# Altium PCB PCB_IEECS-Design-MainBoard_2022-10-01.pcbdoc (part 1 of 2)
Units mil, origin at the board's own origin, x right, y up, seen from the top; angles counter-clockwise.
Board outline 4144.93 x 4242 mil, 2 copper layers (Top Layer, Bottom Layer); 143 components, 136 nets, 539 pads, 189 vias.
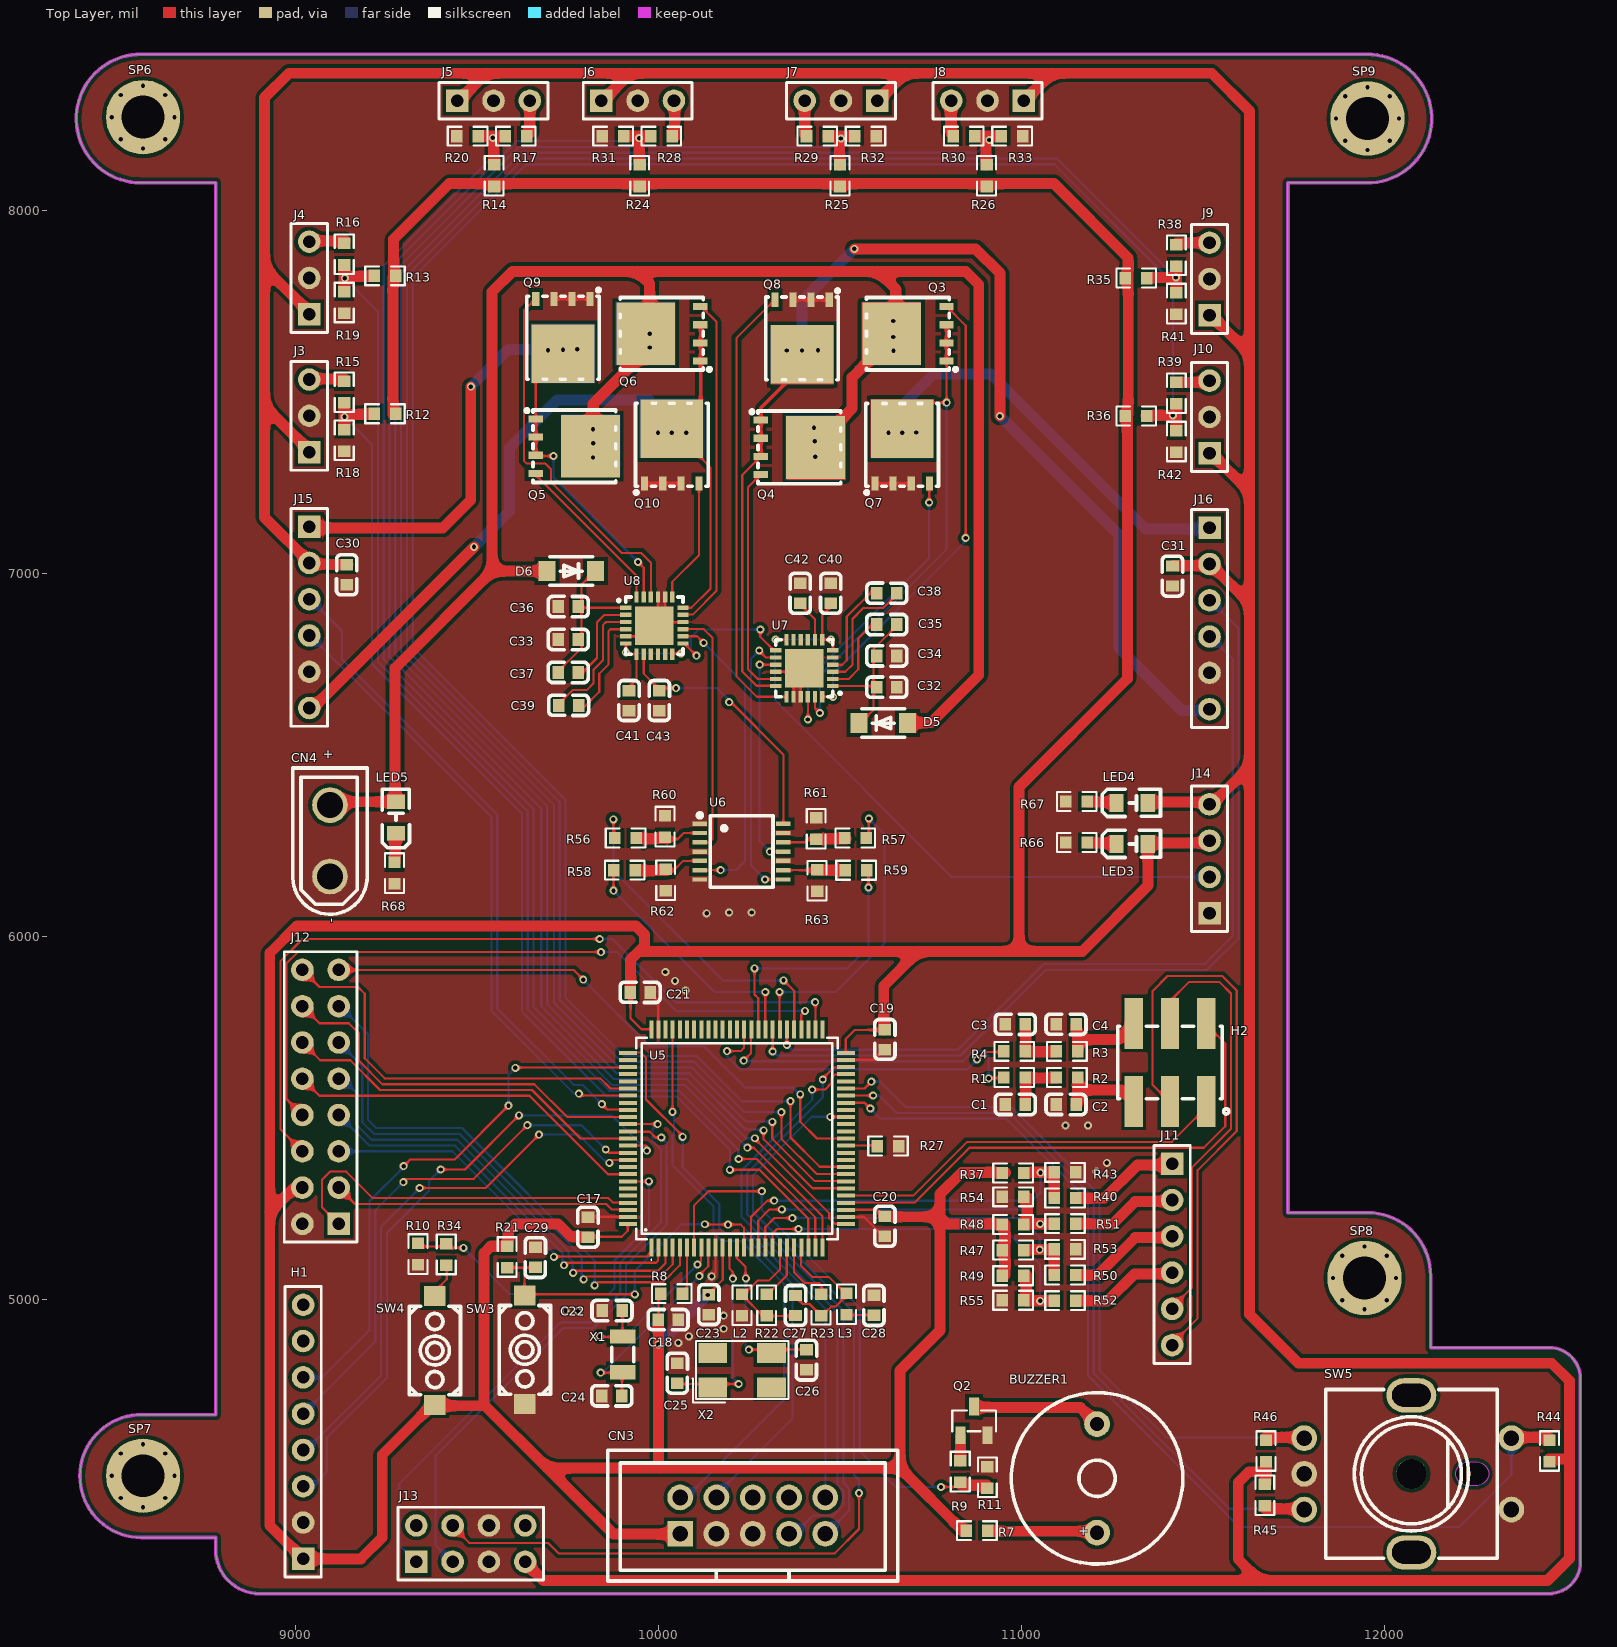
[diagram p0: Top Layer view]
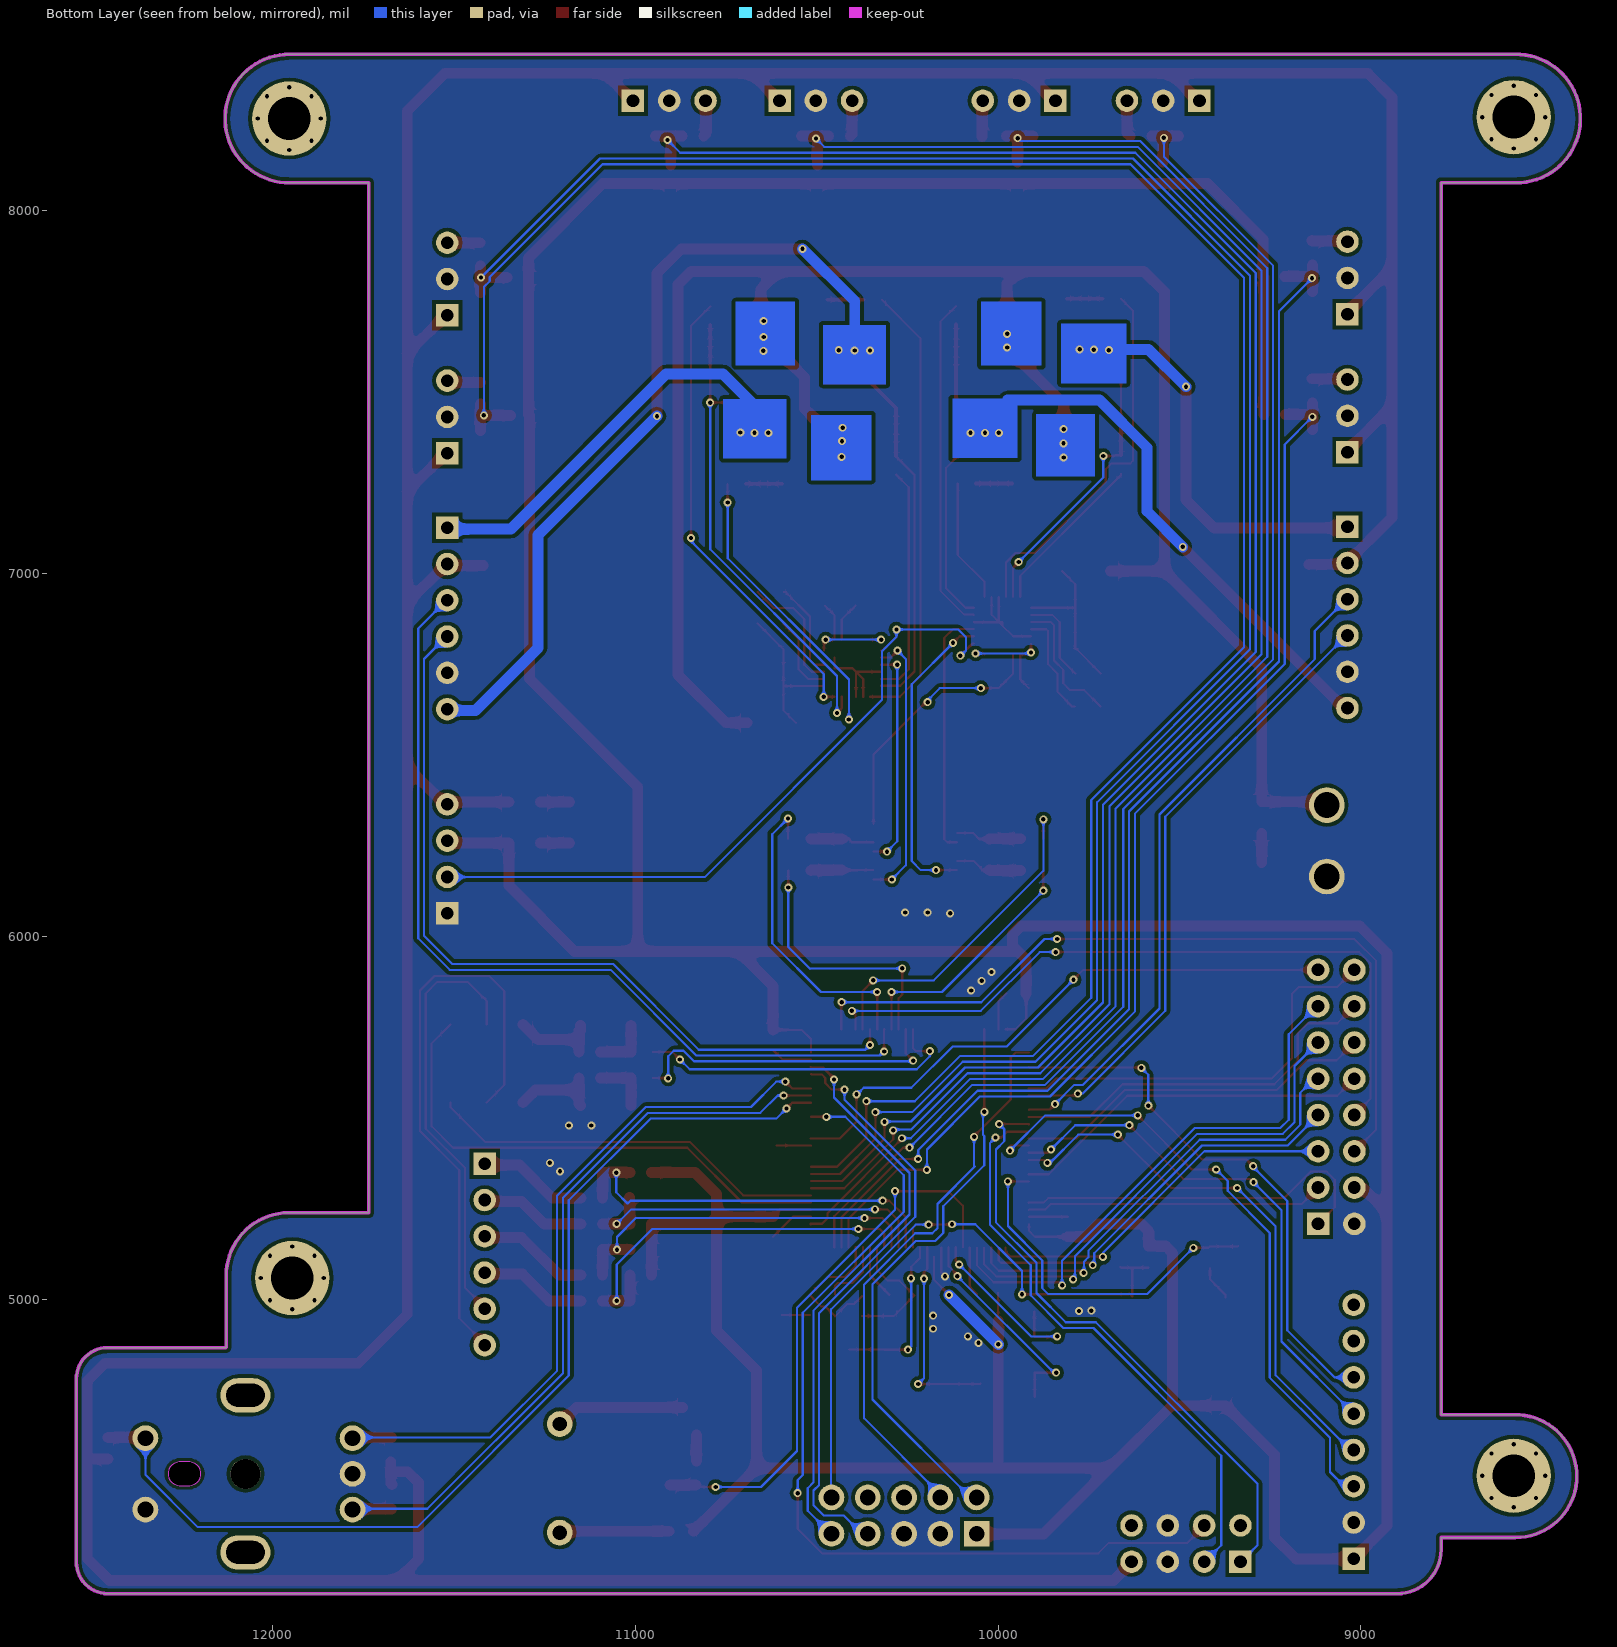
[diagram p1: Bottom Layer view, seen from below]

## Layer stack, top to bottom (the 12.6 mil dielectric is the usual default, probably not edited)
Top Solder: solder mask 0.4, Solder Resist, Dk 3.5
Top Layer: signal copper 1.4
Dielectric1: dielectric 12.6, FR-4, Dk 4.8
Bottom Layer: signal copper 1.4
Bottom Solder: solder mask 0.4, Solder Resist, Dk 3.5

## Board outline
8574.18,4343.58 8778.42,4343.58 8779,4343 8779,4310 ccw(c8900,4310) 8900,4189 12453,4189 ccw(c12453,4276) 12540,4276 12540,4781 ccw(c12454,4781) 12454,4867 12128.3,4867 12127.15,4868.15 12127.15,5065.04 ccw(c11953.18,5065.04) 11955,5239 11734,5239 11734,8077 11950.98,8077 ccw(c11953.18,8254) 11951,8431 8575,8431 ccw(c8572,8254) 8572,8076.97 8779,8076.97 8779,8038 8779,4682 8576,4682 ccw(c8574.18,4512.8)

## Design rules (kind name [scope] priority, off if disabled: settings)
Clearance [All] p1: gap=10 ignorepadtopadclearanceinfootprint=TRUE except(0: Arc-Hole Track-Hole SMDPad-Hole THPad-Hole Via-Hole Fill-Hole Poly-Hole Region-Hole Text-Hole)
Height [All] p1: minheight=0 maxheight=10000 prefheight=10000
PolygonConnect [All] p1: connectstyle=Direct reliefconductorwidth=10 reliefentries=4 polygonreliefangle="90 Angle" airgapwidth=10
RoutingVias [All] p1: holewidth=28 width=50 viastyle="Through Hole" minholewidth=28 minwidth=50 maxholewidth=28 maxwidth=50
SolderMaskExpansion [All] p1: expansion=4
Width [All] p1: maxlimit=30 minlimit=6 preferedwidth=10 minimp=50.000000 maximp=50.000000 favimp=50.000000
29 further rules are at their usual default settings.

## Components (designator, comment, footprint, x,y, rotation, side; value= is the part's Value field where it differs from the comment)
BUZZER1 "TMB12A03" Buzzer 11204,4510.61 r0 top
C1 "1nf" CAP0603 10983.66,5534 r0 top
C2 "100pf" CAP0603 11123.66,5534 r0 top
C3 "1nf" CAP0603 10983.66,5755 r0 top
C4 "100pf" CAP0603 11123.66,5755 r0 top
C17 "50V 100nF" CAP0603 9808,5200 r90 top
C18 "50V 100nF" CAP0603 10027,4941 r0 top
C19 "50V 100nF" CAP0603 10620,5715 r270 top
C20 "50V 100nF" CAP0603 10620,5200 r270 top
C21 "50V 100nF" CAP0603 9950,5843 r0 top
C22 "50V 12pF" CAP0603 9872.44,4966 r0 top
C23 "50V 100nF" CAP0603 10135,4984.44 r270 top
C24 "50V 12pF" CAP0603 9872,4731 r0 top
C25 "50V 20pF" CAP0603 10048,4795.44 r270 top
C26 "50V 20pF" CAP0603 10410,4834 r90 top
C27 "50V 100nF" CAP0603 10374,4982 r270 top
C28 "50V 100nF" CAP0603 10596,4984.44 r90 top
C29 "100nF" CAP0603 9663,5116.56 r90 top
C30 "100nF" CAP0603 9143.16,6998 r90 top
C31 "100nF" CAP0603 11418.7,6994.39 r90 top
C32 "100nF" CAP0603 10627,6690.03 r180 top
C33 "100nF" CAP0603 9752,6815.31 r0 top
C34 "10uF" CAP0603 10627,6776.36 r180 top
C35 "16V 1uF" CAP0603 10627,6862.7 r180 top
C36 "10uF" CAP0603 9752,6905.97 r0 top
C37 "16V 1uF" CAP0603 9752,6724.66 r0 top
C38 "100nF" CAP0603 10627,6949.03 r180 top
C39 "100nF" CAP0603 9753,6634 r0 top
C40 "6.3V 1uF" CAP0603 10477,6947 r90 top
C41 "6.3V 1uF" CAP0603 9915,6649 r270 top
C42 "6.3V 1uF" CAP0603 10393,6947 r90 top
C43 "6.3V 1uF" CAP0603 9998.55,6649 r270 top
CN3 "X9555WV-2×05-PTV01" Download 10259,4416 r0 top
CN4 "XT30UPB-M" XT30 9082,6276.32 r0 top
D5 "1N5819HW-7-F" Diode 10627,6595 r0 top
D6 "1N5819HW-7-F" Diode 9751,7000 r180 top
H1 "HDR-F-2.54_1x8" Pin1X8 9010,4637 r270 top
H2 "双排针2*3P  脚距2.54MM  贴片" Pin2X3 11396,5652 r0 top
J3 "HDR-M-2.54_1x3" Pin1X3 9039.14,7432.86 r0 top
J4 "HDR-M-2.54_1x3" Pin1X3 9039.14,7812.86 r0 top
J5 "HDR-M-2.54_1x3" Pin1X3 9542.86,8301.14 r270 top
J6 "HDR-M-2.54_1x3" Pin1X3 9939.86,8301.14 r270 top
J7 "HDR-M-2.54_1x3" Pin1X3 10504.14,8305.43 r90 top
J8 "HDR-M-2.54_1x3" Pin1X3 10908.04,8305.43 r90 top
J9 "HDR-M-2.54_1x3" Pin1X3 11520,7809.86 r0 top
J10 "HDR-M-2.54_1x3" Pin1X3 11520,7429.86 r0 top
J11 "HDR-M-2.54_1x6" Pin1x6 11407,5120 r270 top
J12 "HDR-M-2.54_2x8" Pin2x8 9059,5543 r270 top
J13 "HDR-M-2.54_2x4" Pin2X4 9483,4328 r0 top
J14 "HDR-M-2.54_1x4" Pin1X4 11522,6213.59 r270 top
J15 "HDR-M-2.54_1x6" Pin1x6 9029.14,6875.74 r270 top
J16 "HDR-M-2.54_1x6" Pin1x6 11510,6872.74 r270 top
L2 "0Ω" RES0603 10231,4976 r90 top
L3 "0Ω" RES0603 10519,4979 r90 top
LED3 "FC-2012HRK-620D" LED0603 11304.86,6257.59 r0 top
LED4 "FC-2012HRK-620D" LED0603 11304.86,6370.59 r0 top
LED5 "FC-2012HRK-620D" LED0603 9273.41,6327.86 r90 top
Q2 "S8050_C908252" TRIODE 10868,4655 r0 top
Q3 "TPH1R403NL" MOS 10712.55,7673 r180 top
Q4 "TPH1R403NL" MOS 10362,7336 r0 top
Q5 "TPH1R403NL" MOS 9741.88,7339 r0 top
Q6 "TPH1R403NL" MOS 10034,7673 r180 top
Q7 "TPH1R403NL" MOS 10683,7329 r90 top
Q8 "TPH1R403NL" MOS 10383,7674 r270 top
Q9 "TPH1R403NL" MOS 9724,7676 r270 top
Q10 "TPH1R403NL" MOS 10048,7329.12 r90 top
R1 "4.7k" RES0603 10972,5609.97 r0 top
R2 "47k" RES0603 11117,5610 r0 top
R3 "47k" RES0603 11117,5682 r0 top
R4 "4.7k" RES0603 10972,5682 r0 top
R7 "10" RES0603 10869,4361 r0 top
R8 "0" RES0603 10028,5014 r0 top
R9 "4.7K" RES0603 10832.51,4517.56 r90 top
R10 "10k" RES0603 9338,5117 r90 top
R11 "10K" RES0603 10903.99,4517.56 r270 top
R12 "11k" RES0603 9237.66,7439 r0 top
R13 "11k" RES0603 9237.66,7819 r0 top
R14 "11k" RES0603 9545,8104.35 r270 top
R15 "1k" RES0603 9131.82,7508 r270 top
R16 "1k" RES0603 9131.82,7888 r270 top
R17 "1k" RES0603 9614,8207.18 r180 top
R18 "1.65k" RES0603 9135,7359.35 r90 top
R19 "1.65k" RES0603 9135,7739.35 r90 top
R20 "1.65k" RES0603 9465.34,8204 r0 top
R21 "10K" RES0603 9584,5109 r90 top
R22 "0" RES0603 10299,4976 r90 top
R23 "0" RES0603 10449,4977 r90 top
R24 "11k" RES0603 9946,8104.35 r270 top
R25 "11k" RES0603 10498,8104.35 r270 top
R26 "11k" RES0603 10901.89,8104.35 r270 top
R27 "10k" RES0603 10639.66,5424 r180 top
R28 "1k" RES0603 10015,8207.18 r180 top
R29 "1k" RES0603 10429,8204 r0 top
R30 "1k" RES0603 10832.89,8204 r0 top
R31 "1.65k" RES0603 9866.34,8204 r0 top
R32 "1.65k" RES0603 10577.66,8207.18 r180 top
R33 "1.65k" RES0603 10981.55,8207.18 r180 top
R34 "1k" RES0603 9416,5116 r90 top
R35 "11k" RES0603 11323.55,7816 r180 top
R36 "11k" RES0603 11323.55,7436 r180 top
R37 "11k" RES0603 10984.34,5350 r180 top
R38 "1k" RES0603 11424.86,7885 r270 top
R39 "1k" RES0603 11424.86,7505 r270 top
R40 "3.4k" RES0603 11127.34,5280.81 r180 top
R41 "1.65k" RES0603 11428.04,7736.35 r90 top
R42 "1.65k" RES0603 11428.04,7356.35 r90 top
R43 "1.4k" RES0603 11127.34,5351.52 r180 top
R44 "10K" RES0603 12453,4589.99 r270 top
R45 "10K" RES0603 11672,4452.45 r90 top
R46 "10K" RES0603 11672,4589.99 r270 top
R47 "11k" RES0603 10984.34,5137.41 r180 top
R48 "11k" RES0603 10984.34,5208.11 r180 top
R49 "11k" RES0603 10984.34,5066.7 r180 top
R50 "3.4k" RES0603 11127.34,5068.7 r180 top
R51 "3.4k" RES0603 11127.34,5210.11 r180 top
R52 "3.4k" RES0603 11127.34,4998 r180 top
R53 "1.4k" RES0603 11127.34,5139.41 r180 top
R54 "1.4k" RES0603 10968.63,5281 r0 top
R55 "1.4k" RES0603 10968.63,4996 r0 top
R56 "100" RES0603 9900.76,6270 r0 top
R57 "100" RES0603 10534,6270 r0 top
R58 "100" RES0603 9898.35,6181.32 r0 top
R59 "100" RES0603 10536,6181 r0 top
R60 "10k" RES0603 10019,6295 r90 top
R61 "10k" RES0603 10432.28,6305 r270 top
R62 "10k" RES0603 10017.41,6163 r270 top
R63 "10k" RES0603 10438,6146 r90 top
R66 "330" RES0603 11143.86,6257.59 r0 top
R67 "330" RES0603 11143.86,6370.59 r0 top
R68 "1k" RES0603 9273.41,6166.86 r90 top
SP6 "M3铜柱" M3-MountHole-Plated 8579,8258 r0 top (schematic designator SP2)
SP7 "M3铜柱" M3-MountHole-Plated 8579,4514 r0 top (schematic designator SP2)
SP8 "M3铜柱" M3-MountHole-Plated 11945,5059 r0 top (schematic designator SP2)
SP9 "M3铜柱" M3-MountHole-Plated 11953.18,8254 r0 top (schematic designator SP2)
SW3 "K2-1107ST-A4SW-06" Key 9631,4870 r270 top
SW4 "K2-1107ST-A4SW-06" Key 9383,4868 r270 top
SW5 "EC11L1524E03" encode_key 12064.13,4521.22 r0 top
U5 "CH32V307" CH32V307 10226.1,5441.2 r0 top
U6 "SN74HC125PWR" SN74HC125PWR 10252.92,6224 r0 top
U7 "DRV8701ERGET" DRV8701E 10404.57,6737 r0 top
U8 "DRV8701ERGET" DRV8701E 9984.69,6859 r180 top
X1 "32.768kHz" OSC2 9896.76,4848 r270 top
X2 "8MHz" OSC1 10232,4814 r0 top

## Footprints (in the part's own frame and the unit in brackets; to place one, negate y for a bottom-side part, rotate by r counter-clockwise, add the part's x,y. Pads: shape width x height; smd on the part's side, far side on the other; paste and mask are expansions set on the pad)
Buzzer [mm]
  round 1.8 hole 1: 1(0.102,-3.897) 2(0.102,3.703)
  silkscreen extent -5.89,-6.1 6.1,5.9, body extent -6.13,-5.89 5.87,6.11, height 9.51
CAP0603 [mm]
  rect 0.8x0.9 smd: 1(-0.725,0.076) 2(0.675,0.076)
  silkscreen extent -1.43,-0.63 1.36,0.79, body extent -0.93,-0.32 0.67,0.48, height 0.8
CH32V307 [mm] "TSQFP, 100-Leads, Body 14.00x14.00mm, Pitch 0.50mm, IPC Medium Density"
  rect 0.28x1.287 smd: 1(-6.263,-7.574) 2(-5.763,-7.574) 3(-5.263,-7.574) 4(-4.763,-7.574) 5(-4.263,-7.574) 6(-3.763,-7.574) 7(-3.263,-7.574) 8(-2.763,-7.574) 9(-2.263,-7.574) 10(-1.763,-7.574) 11(-1.263,-7.574) 12(-0.763,-7.574) 13(-0.263,-7.574) 14(0.237,-7.574) 15(0.737,-7.574) 16(1.237,-7.574) 17(1.737,-7.574) 18(2.237,-7.574) 19(2.737,-7.574) 20(3.237,-7.574) 21(3.737,-7.574) 22(4.237,-7.574) 23(4.737,-7.574) 24(5.237,-7.574) 25(5.737,-7.574) 51(5.737,7.683) 52(5.237,7.683) 53(4.737,7.683) 54(4.237,7.683) 55(3.737,7.683) 56(3.237,7.683) 57(2.737,7.683) 58(2.237,7.683) 59(1.737,7.683) 60(1.237,7.683) 61(0.737,7.683) 62(0.237,7.683) 63(-0.263,7.683) 64(-0.763,7.683) 65(-1.263,7.683) 66(-1.763,7.683) 67(-2.263,7.683) 68(-2.763,7.683) 69(-3.263,7.683) 70(-3.763,7.683) 71(-4.263,7.683) 72(-4.763,7.683) 73(-5.263,7.683) 74(-5.763,7.683) 75(-6.263,7.683)
  rect 1.287x0.28 smd: 26(7.365,-5.946) 27(7.365,-5.446) 28(7.365,-4.946) 29(7.365,-4.446) 30(7.365,-3.946) 31(7.365,-3.446) 32(7.365,-2.946) 33(7.365,-2.446) 34(7.365,-1.946) 35(7.365,-1.446) 36(7.365,-0.946) 37(7.365,-0.446) 38(7.365,0.054) 39(7.365,0.554) 40(7.365,1.054) 41(7.365,1.554) 42(7.365,2.054) 43(7.365,2.554) 44(7.365,3.054) 45(7.365,3.554) 46(7.365,4.054) 47(7.365,4.554) 48(7.365,5.054) 49(7.365,5.554) 50(7.365,6.054) 76(-7.892,6.054) 77(-7.892,5.554) 78(-7.892,5.054) 79(-7.892,4.554) 80(-7.892,4.054) 81(-7.892,3.554) 82(-7.892,3.054) 83(-7.892,2.554) 84(-7.892,2.054) 85(-7.892,1.554) 86(-7.892,1.054) 87(-7.892,0.554) 88(-7.892,0.054) 89(-7.892,-0.446) 90(-7.892,-0.946) 91(-7.892,-1.446) 92(-7.892,-1.946) 93(-7.892,-2.446) 94(-7.892,-2.946) 95(-7.892,-3.446) 96(-7.892,-3.946) 97(-7.892,-4.446) 98(-7.892,-4.946) 99(-7.892,-5.446) 100(-7.892,-5.946)
  silkscreen extent -7.31,-8.46 6.79,7.11, body extent -8.25,-7.95 7.75,8.05, height 1.5
Diode [mm]
  rect 1.2x1.4 smd: 1(1.499,-0.177) 2(-1.901,-0.177)
  silkscreen extent -1.7,-1.18 1.3,0.82, body extent -1.95,-1.15 1.7,0.65, height 0.81
Download [mm]
  rect 1.8x1.8 hole 1.1: 1(-5.08,-1.575)
  round 1.8 hole 1.1: 2(-5.08,0.965) 3(-2.54,-1.575) 4(-2.54,0.965) 5(0,-1.575) 6(0,0.965) 7(2.54,-1.575) 8(2.54,0.965) 9(5.08,-1.575) 10(5.08,0.965)
  silkscreen extent -10.14,-4.88 10.14,4.27, body extent -9.83,-4.74 10.47,4.16, height 9.2
DRV8701E [mm]
  rect 0.8x0.3 smd: 1(1.914,-1.193) 2(1.914,-0.694) 3(1.914,-0.194) 4(1.914,0.307) 5(1.914,0.807) 6(1.914,1.308) 13(-2.086,1.307) 14(-2.086,0.806) 15(-2.086,0.306) 16(-2.086,-0.194) 17(-2.086,-0.692) 18(-2.086,-1.193)
  rect 0.3x0.8 smd: 7(1.164,2.057) 8(0.664,2.057) 9(0.163,2.057) 10(-0.337,2.057) 11(-0.837,2.057) 12(-1.336,2.057) 19(-1.336,-1.944) 20(-0.836,-1.944) 21(-0.336,-1.944) 22(0.163,-1.944) 23(0.663,-1.944) 24(1.163,-1.944)
  rect 2.7x2.7 smd: 25(-0.084,0.058)
  silkscreen extent -2.09,-1.94 2.51,2.06, body extent -2.01,-2.07 2.01,1.95, height 1.02
encode_key [mm] "编码器开关"
  oval 3.5x2.4 hole 1.6 slot 2.7 at 0 deg: 6(0.253,5.449) 7(0.253,-5.551)
  round 1.8 hole 1.1: A(-7.247,2.449) B(-7.247,-2.551) C(-7.247,-0.051) D(7.253,2.449) E(7.253,-2.551)
  round 2.1 hole 2.1 unplated: ""(0.253,-0.051)
  Keep-Out Layer board cut-out: 4.133,0.779 4.895,0.779 4.998,0.771 5.194,0.704 5.368,0.591 5.508,0.439 5.606,0.258 5.657,0.057 5.657,-0.15 5.606,-0.35 5.508,-0.532 5.368,-0.684 5.194,-0.797 4.998,-0.864 4.895,-0.872 4.895,-0.872 4.133,-0.872 4.03,-0.864 3.834,-0.797 3.661,-0.684 3.521,-0.532 3.422,-0.35 3.371,-0.15 3.371,0.057 3.422,0.258 3.521,0.439 3.661,0.591 3.834,0.704 4.03,0.771 4.133,0.779
  silkscreen extent -5.75,-5.95 6.25,5.85, body extent -7.51,-6.86 7.39,5.98, height 21.49
Key [mm]
  rect 1.4x1.5 smd: 1(-3.571,0) 2(4.029,0)
  silkscreen extent -2.87,-1.8 3.33,1.8, body extent -4.44,-1.93 4.27,1.67, height 2.6
LED0603 [mm]
  rect 1x1.25 smd: 1(-1.104,-0.061) 2(1.096,-0.061)
  silkscreen extent -2.1,-1.01 1.98,0.9, body extent -1.01,-0.75 1.01,0.51, height 1.01
M3-MountHole-Plated [mm]
  round 5.2 hole 3: 1(0,0)
MOS [mm]
  rect 1x0.5 smd: 1(-2.051,2.21) 2(-2.051,0.94) 3(-2.051,-0.33) 4(-2.051,-1.6)
  round 0 smd: 5(1.499,0.305)
  rect 4.1x4.4 smd: 5(1.778,0.305)
  silkscreen extent -2.8,-2.24 3.55,2.92, body extent -2.24,-2.16 3.58,2.76, height 1.11
OSC1 [mm]
  rect 2x1.4 smd: 1(-2.101,-1.429) 2(1.999,-1.429) 3(1.999,0.971) 4(-2.101,0.971)
  silkscreen extent -3.51,-2.49 3.19,1.8, body extent -2.5,-1.73 2.5,1.47, height 1.12
OSC2 [mm]
  rect 1x1.8 smd: 1(1.245,0.102) 2(-1.255,0.102)
  silkscreen extent -0.51,-0.66 0.5,0.86, body extent -1.6,-0.62 1.6,1.4, height 0.76
Pin1X3 [mil]
  rect 62x62 hole 35: 1(-2.14,-98)
  round 62 hole 35: 2(-2.14,2) 3(-2.14,102)
  silkscreen extent -52,-148 48,152, body extent -52,-148 48,152, height 335
Pin1X4 [mil]
  rect 62x62 hole 35: 1(149.41,-4.14)
  round 62 hole 35: 2(49.41,-4.14) 3(-50.59,-4.14) 4(-150.59,-4.14)
  silkscreen extent -201,-54 199,46, body extent -205,-54 195,46, height 335
Pin1x6 [mil]
  rect 62x62 hole 35: 1(-253.74,7.86)
  round 62 hole 35: 2(-153.74,7.86) 3(-53.74,7.86) 4(46.26,7.86) 5(146.26,7.86) 6(246.26,7.86)
  silkscreen extent -304,-42 296,58, body extent -305,-45 295,125, height 335
Pin1X8 [mil]
  rect 62x62 hole 35: 1(352,10)
  round 62 hole 35: 2(252,10) 3(152,10) 4(52,10) 5(-48,10) 6(-148,10) 7(-248,10) 8(-348,10)
  silkscreen extent -398,-40 402,60, body extent -395,-40 405,60, height 333
Pin2X3 [mil]
  rect 50x140.16 smd: 1(113,-106.48) 2(113,108.48) 3(13,-106.48) 4(13,108.48) 5(-87,-106.48) 6(-87,108.48)
  silkscreen extent -131,-141 175,101, body extent -135,-153 165,123, height 534
Pin2X4 [mil]
  rect 62x62 hole 35: 1(-151,-51)
  round 62 hole 35: 2(-151,49) 3(-51,-51) 4(-51,49) 5(49,-51) 6(49,49) 7(149,-51) 8(149,49)
  silkscreen extent -201,-101 199,99, body extent -200,-100 200,100, height 333
Pin2x8 [mil]
  rect 62x62 hole 35: 1(335,59)
  round 62 hole 35: 2(335,-41) 3(235,59) 4(235,-41) 5(135,59) 6(135,-41) 7(35,59) 8(35,-41) 9(-65,59) 10(-65,-41) 11(-165,59) 12(-165,-41) 13(-265,59) 14(-265,-41) 15(-365,59) 16(-365,-41)
  silkscreen extent -415,-91 385,109, body extent -415,-95 385,105, height 333
RES0603 [mil]
  rect 31.75x34.02 smd: 1(-21.8,1.59) 2(37.51,1.59)
  silkscreen extent -47,-24 62,28, body extent -21,-16 42,16, height 31
SN74HC125PWR [mil]
  rect 39x12 smd: 1(-139.92,86.77) 2(-139.92,61.18) 3(-139.92,35.59) 4(-139.92,10) 5(-139.92,-15.59) 6(-139.92,-41.18) 7(-139.92,-66.77) 8(90.39,-66.77) 9(90.39,-41.18) 10(90.39,-15.59) 11(90.39,10) 12(90.39,35.59) 13(90.39,61.18) 14(90.39,86.77)
  silkscreen extent -145,-88 62,116, body extent -143,-88 93,108, height 43
TRIODE [mm]
  rect 0.7x1.25 smd: 1(-0.927,-0.744) 2(0.973,-0.744) 3(0.023,1.256)
  silkscreen extent -1.5,-0.47 1.55,0.98, body extent -1.42,-1 1.47,1.5, height 1.05
XT30 [mm]
  round 2.5 hole 1.8: 1(0.305,-2.822) 2(0.305,2.178)
  silkscreen extent -2.3,-5.46 2.91,4.78, body extent -2.3,-5.35 5.84,4.85, height 10.7

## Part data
SP6 SP7 SP8 SP9: library part 铜柱小焊盘, "铜柱"

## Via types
v1: diameter 22, hole 12, Top Layer to Bottom Layer, tented both sides, 157 vias
v2: diameter 23.62, hole 11.81, Top Layer to Bottom Layer, 32 vias

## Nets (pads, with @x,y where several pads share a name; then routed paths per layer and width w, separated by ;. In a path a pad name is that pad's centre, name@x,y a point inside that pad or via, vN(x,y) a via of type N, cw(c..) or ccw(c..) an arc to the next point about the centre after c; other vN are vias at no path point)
ADC-0: J11.1 R40.1 | length 305.2
  Top Layer w30: R40.1@11149,5278.81 11227.81,5278.81 11319,5370 11411.12,5370 J11.1@11414.86,5373.74
ADC-0-OUT: R37.1 R40.2 R43.2 U5.15 | length 1115.7
  Top Layer w6: U5.15@10254.37,5143.67 10254.37,5226.93 10299.44,5272 v1(10318,5272)
  Top Layer w30: R37.1@11014.66,5350 11089.21,5350 11089.69,5349.52 R40.2@11089.69,5278.81
  Bottom Layer w6: v1(10318,5272) 11013,5272 11021,5264 11052,5295 v1(11052,5349)
ADC-1: J11.2 R51.1 | length 283.6
  Top Layer w30: R51.1@11149,5208.11 11251.11,5208.11 11313,5270 J11.2@11407,5270
ADC-1-OUT: R48.1 R51.2 R54.2 U5.16 | length 1029
  Top Layer w6: U5.16@10274.06,5143.67 10274.06,5217.06 10305,5248 v1(10339.25,5248)
  Top Layer w30: R54.2@11015.76,5281 11015.76,5209.87 11014,5208.11 R51.2@11089.69,5208.11
  Bottom Layer w6: v1(10339.25,5248) 11011,5248 v1(11051,5208)
ADC-2: J11.3 R50.1 | length 300.8
  Top Layer w30: R50.1@11149,5066.7 11209.7,5066.7 11313,5170 J11.3@11407,5170
ADC-2-OUT: R47.1 R50.2 R53.2 U5.17 | length 1024.7
  Top Layer w6: U5.17@10293.74,5143.67 10293.74,5198.74 10319,5224 v1(10368,5224)
  Top Layer w30: R47.1@11014,5137.41 11089.69,5137.41 R50.2@11089.69,5066.7
  Bottom Layer w6: v1(10368,5224) 10998,5224 11050,5172 v1(11050,5137)
ADC-3: J11.4 R52.1 | length 288.7
  Top Layer w30: R52.1@11149,4996 11237,4996 11311,5070 J11.4@11407,5070
ADC-3-OUT: R49.1 R52.2 R55.2 U5.18 | length 1067.5
  Top Layer w6: U5.18@10313.43,5143.67 10313.43,5181.43 10326,5194 v1(10385,5194)
  Top Layer w30: R49.1@11014,5066.7 11014,4996 v1(11051,4996) R52.2@11089.69,4996
  Bottom Layer w6: v1(10385,5194) 10953,5194 11051,5096 v1(11051,4996)
ADC-SONAR-0: R12.1 R15.2 R18.2 U5.23 | length 3127.4
  Top Layer w6: v1(10196,5357) 10277.9,5357 10411.85,5223.05 U5.23@10411.85,5143.67
  Top Layer w30: R18.2@9133.41,7396.86 R15.2@9133.41,7470.49 ; 9135,7444 9140,7439 R12.1@9208,7439
  Bottom Layer w6: v1(9134,7432) 9210,7356 9210,6751 9623,6338 9623,5793 9857,5559 10050,5559 10196,5413 v1(10196,5357)
ADC-SONAR-1: R13.1 R16.2 R19.2 U5.24 | length 3507.8
  Top Layer w6: v1(10220.24,5387) 10270.52,5387 10431.54,5225.99 U5.24@10431.54,5143.67
  Top Layer w30: R19.2@9133.41,7776.86 R16.2@9133.41,7850.49 ; v1(9135,7814) 9135,7822 9138,7819 R13.1@9210,7819
  Bottom Layer w6: v1(9135,7814) 9226,7723 9226,6757.63 9639,6344.63 9639,5799.63 9863.63,5575 10056.63,5575 10220,5411.63 10220,5387.24 v1(10220.24,5387)
ADC-SONAR-2: R14.1 R17.2 R20.2 U5.25 | length 3952.6
  Top Layer w6: v1(10244,5418) 10262.15,5418 10451.22,5228.93 U5.25@10451.22,5143.67
  Top Layer w30: R20.2@9502.86,8205.59 R17.2@9576.49,8205.59 ; v1(9543,8201) 9545,8199 R14.1@9545,8134
  Bottom Layer w6: v1(9543,8201) 9543,8149.25 9242,7848.25 9242,6764.25 9655,6351.25 9655,5806.25 9870.25,5591 10071,5591 v1(10244,5418)
ADC-SONAR-3: R24.1 R28.2 R31.2 U5.26 | length 4287.2
  Top Layer w6: v1(10265,5444) 10265,5442.37 10470,5237.37 10470,5223.64 10485.35,5208.29 10516.07,5208.29 U5.26@10516.07,5207.11
  Top Layer w30: R31.2@9903.86,8205.59 R28.2@9977.49,8205.59 ; R24.1@9946,8134 v1(9946,8200) v1@9950,8204
  Bottom Layer w6: v1(9946,8200) 9938,8192 9608.37,8192 9258,7841.63 9258,6770.88 9676,6352.88 9676,5807.88 9876.88,5607 10077.63,5607 10240.63,5444 v1(10265,5444)
ADC-SONAR-4: R25.1 R29.2 R32.2 U5.31 | length 4769.7
  Top Layer w6: v1(10289,5466) 10289,5441 10423.79,5306.21 U5.31@10515.33,5306.21
  Top Layer w30: R29.2@10466.51,8205.59 R32.2@10540.14,8205.59 R32.2@10541.41,8205.59 ; R25.1@10498,8126.35 10498,8195.29 v1(10501.71,8199)
  Bottom Layer w6: v1(10289,5466) 10287,5468 10239.25,5468 10084.25,5623 9883.51,5623 9693,5813.51 9693,6358.51 9274,6777.51 9274,7835 9615,8176 10478.71,8176 v1(10501.71,8199)
ADC-SONAR-5: R26.1 R30.2 R33.2 U5.32 | length 5133.3
  Top Layer w6: v1(10313,5489) 10313,5443 10430.11,5325.89 U5.32@10515.33,5325.89
  Top Layer w30: R30.2@10870.4,8205.59 R33.2@10944.04,8205.59 ; R26.1@10901.89,8126.14 v1@10901.89,8193.12
  Bottom Layer w6: v1(10313,5489) 10312,5490 10239.88,5490 10090.88,5639 9890.14,5639 9711,5818.14 9711,6363.14 9290,6784.14 9290,7828.37 9621.63,8160 10876,8160 v1(10911,8195)
ADC-SONAR-6: R35.1 R38.2 R41.2 U5.33 | length 5734.4
  Top Layer w6: v1(10338,5516) 10338,5443 10435.42,5345.58 U5.33@10515.33,5345.58
  Top Layer w30: R35.1@11353.2,7816 v1(11424.86,7816) ; R41.2@11426.45,7773.86 R38.2@11426.45,7847.49
  Bottom Layer w6: v1(10338,5516) 10236.51,5516 10097.51,5655 9896.76,5655 9727,5824.76 9727,6369.76 9306,6790.76 9306,7821.75 9628.25,8144 11096.86,8144 v1(11424.86,7816)
ADC-SONAR-7: R36.1 R39.2 R42.2 U5.34 | length 6057.3
  Top Layer w6: v1(10363,5546) 10363,5446 10443.74,5365.26 U5.34@10515.33,5365.26
  Top Layer w30: R36.1@11343.2,7436 v1(11416.86,7436) v1@11418.86,7438 ; R42.2@11426.45,7393.86 R39.2@11426.45,7467.49
  Bottom Layer w6: v1(10363,5546) 10229.14,5546 10104.14,5671 9903.39,5671 9743,5831.39 9743,6376.39 9322,6797.39 9322,7815.12 9634.88,8128 11090.23,8128 11400.86,7817.37 11400.86,7806.06 11416.86,7790.06 v1(11416.86,7436)
B3: H1.3 U5.89 | length 1778.8
  Top Layer w6: v1(9399,5358) 9466,5358 v1(9615,5507) ; U5.89@9915.41,5423.65 9964.35,5423.65 9967,5421 v1(9967,5410)
  Bottom Layer w6: H1.3@9020,4485 9046,4485 9085,4524 9085,4618.37 9251,4784.37 9251,5183.06 9367,5299.06 9367,5326 v1(9399,5358) ; v1(9615,5507) 9870,5507 v1(9967,5410)
B4: H1.5 U5.90 | length 1468.8
  Top Layer w6: v1(9296,5323) 9305,5332 9490,5332 v1(9638,5480) ; v1(9854,5413) 9854,5412 9862.04,5403.96 U5.90@9915.41,5403.96
  Bottom Layer w6: H1.5@9020,4685 9219,4884 9219,5246 v1(9296,5323) ; v1(9638,5480) 9787,5480 v1(9854,5413)
B5: H1.4 U5.91 | length 1531.3
  Top Layer w6: v1(9341,5307) 9523,5307 v1(9670,5454) ; v1(9864,5376) 9872.28,5384.28 U5.91@9915.41,5384.28
  Bottom Layer w6: H1.4@9020,4585 9029,4585 9235,4791 9235,5201 v1(9341,5307) ; v1(9670,5454) 9779.06,5454 9857.06,5376 v1(9864,5376)
B7: J12.10 U5.93 | length 1006.4
  Top Layer w6: J12.10@9018,5608 9065,5561 9644,5561 9860.09,5344.91 U5.93@9915.41,5344.91
B13: J12.6 U5.52 | length 2195.6
  Top Layer w6: J12.6@9018,5408 8958,5468 8958,5932.85 9018.15,5993 v1(9837,5993) ; v1(10431,5819) 10432.28,5817.72 U5.52@10432.28,5743.67
  Bottom Layer w6: v1(9837,5993) 9872,5993 10046,5819 v1(10431,5819)
B15: J12.8 U5.54 | length 2006.8
  Top Layer w6: J12.8@9018,5508 8974,5552 8974,5926.23 9004.77,5957 v1(9841,5957) ; U5.54@10392.91,5743.67 10392.91,5784.91 v1(10403,5795) v1@10397,5795
  Bottom Layer w6: v1(9841,5957) 9885.37,5957 10047.37,5795 v1(10403,5795)
BOOT0: R10.2 R34.2 U5.94 | length 992.7
  Top Layer w6: R10.2@9338,5146.66 9339,5145.66 9416,5145.66 9419.66,5142 v1(9462,5142) ; U5.94@9915.41,5325.22 v1(9972.78,5325.22) v1@9973,5325
  Bottom Layer w6: v1(9462,5142) 9589.5,5014.5 9861.5,5014.5 9878,5031 9878,5107.25 9972.78,5202.03 v1(9972.78,5325.22)
C10: H1.6 U5.78 | length 1509.7
  Top Layer w6: v1(9297,5367) 9314,5384 9314,5385 9437,5385 v1(9586,5534) ; v1(9605,5638) 9606.01,5639.01 9914.23,5639.01 U5.78@9915.41,5640.18
  Bottom Layer w6: H1.6@9020,4785 9073,4785 9203,4915 9203,5271 9297,5365 v1(9297,5367) ; v1(9586,5534) 9586,5619 v1(9605,5638)
C13: R9.1 R11.2 U5.7 | length 1538.8
  Top Layer w6: U5.7@10096.89,5143.67 10096.89,5257.89 10137,5298 v1(10284,5298) ; v1(10778,4483) 10827.61,4483 R9.1@10832.51,4487.9
  Top Layer w30: R9.1@10832.51,4487.9 R11.2@10903.99,4487.9
  Bottom Layer w6: v1(10284,5298) 10284,5247 10554,4977 10554,4582 10653,4483 v1(10778,4483)
D0: J12.16 U5.81 | length 1137
  Top Layer w6: J12.16@9018,5908 9065,5861 9171,5861 9190,5842 9190,5664.07 9245.07,5609 9839,5609 9866.87,5581.13 U5.81@9915.41,5581.13
D4: J12.14 U5.85 | length 1068.3
  Top Layer w6: J12.14@9018,5808 9065,5761 9146,5761 9174,5733 9174,5657.44 9238.44,5593 9657.25,5593 9747.86,5502.39 U5.85@9915.41,5502.39
D5: J13.1 U5.86 | length 1667.5
  Top Layer w6: U5.86@9915.41,5482.7 9915.7,5483 v1(9997,5483)
  Bottom Layer w6: J13.1@9329,4278 9285,4322 9285,4491.63 9730.37,4937 9813.37,4937 9894,5017.63 9894,5100.63 10006,5212.63 10006,5356.12 10005.84,5356.28 10005.84,5413.22 9983,5436.06 9983,5469 v1(9997,5483)
D6: J13.3 U5.87 | length 1603.6
  Top Layer w6: U5.87@9915.41,5463.02 9916.58,5461.85 9975,5461.85 9990.85,5446 v1(10007,5446)
  Bottom Layer w6: J13.3@9429,4278 9385,4322 9385,4569 9737,4921 9820,4921 9910,5011 9910,5094 10022,5206 10022,5362.75 10021.84,5362.91 10021.84,5431.16 v1(10007,5446)
D7: J12.12 U5.88 | length 1007
  Top Layer w6: J12.12@9018,5708 9067,5659 9149.81,5659 9231.81,5577 9650.63,5577 9784.29,5443.33 U5.88@9915.41,5443.33
DAC-0: H2.2 U5.29 | length 1434.7
  Top Layer w6: U5.29@10515.33,5266.84 10705.46,5266.84 10856.63,5418 11502,5418 11561,5477 11561,5705.48 H2.2@11509,5757.48
DAC-0-OUT: H2.4 J11.5 | length 1211.1
  Top Layer w6: J11.5@11407,4970 11469,5032 11469,5362.37 11577,5470.37 11577,5843 11545,5875 11462,5875 11409,5822 H2.4@11409,5757.48
DAC-1: H2.1 U5.30 | length 1107.6
  Top Layer w6: U5.30@10515.33,5286.52 10702.52,5286.52 10850,5434 11413.94,5434 11509,5529.06 H2.1@11509,5542.52
DAC-1-OUT: H2.3 J11.6 | length 1651
  Top Layer w6: J11.6@11407,4870 11485,4948 11485,5355.75 11593,5463.75 11593,5851 11553,5891 11402,5891 11361,5850 11361,5590.52 H2.3@11409,5542.52
DATA0: J3.3 R15.1 | length 95.3
  Top Layer w30: J3.3@9039,7537 R15.1@9134.34,7537
DATA1: J4.3 R16.1 | length 95.3
  Top Layer w30: J4.3@9040,7917 9134.34,7917 R16.1@9135,7917.66
DATA2: J5.3 R17.1 | length 102.4
  Top Layer w30: R17.1@9635.8,8205.59 9644.86,8214.65 J5.3@9644.86,8303.29 ; R17.1@9643,8214.66 R17.1@9643.66,8214
DATA3: J6.3 R28.1 | length 97.3
  Top Layer w30: J6.3@10044,8301 10044,8204.66 R28.1@10044.66,8204
DATA4: J7.3 R29.1 | length 99.8
  Top Layer w30: J7.3@10402.14,8303.29 10402.14,8210.65 R29.1@10407.2,8205.59
DATA5: J8.3 R30.1 | length 180.1
  Top Layer w30: R30.1@10803.24,8219 10803.89,8219.65 J8.3@10803.89,8299 ; J8.3@10806.04,8303.29 10806.04,8210.65 R30.1@10811.09,8205.59
DATA6: J9.3 R38.1 | length 92.2
  Top Layer w30: R38.1@11427.66,7911.86 J9.3@11517.86,7911.86 ; J9.3@11517.86,7914 J9.3@11519.86,7914
DATA7: J10.3 R39.1 | length 93.5
  Top Layer w30: R39.1@11426.45,7526.8 11512.8,7526.8 J10.3@11517.86,7531.86
DVDD: C43.1 U6.14 U8.8 | length 724.5
  Top Layer w6: U8.8@9958.55,6778 9958.55,6724.43 9998.55,6684.43 v1(10047.57,6684.43) ; v1(10194,6646) 10199,6646 10343.39,6501.61 U6.14@10343.39,6310.77
  Bottom Layer w6: v1(10047.57,6684.43) 10160.57,6684.43 10194,6651 v1(10194,6646)
E0: J12.1 U5.97 | length 1029.1
  Top Layer w6: J12.1@9118,5208 9072,5254 9072,5330 9094,5352 9139,5352 9212,5279 9861.63,5279 9873.29,5267.34 9914.23,5267.34 U5.97@9915.41,5266.17
E1: J12.3 U5.98 | length 822.9
  Top Layer w6: J12.3@9118,5308 9163,5263 9855,5263 9870.34,5247.66 9914.23,5247.66 U5.98@9915.41,5246.48
E2: J12.5 U5.1 | length 1006.8
  Top Layer w6: v1(9711,5117) 9712,5118 9967,5118 9979.52,5130.52 U5.1@9979.52,5143
  Bottom Layer w6: J12.5@9118,5408 9431.31,5408 9711,5128.31 v1(9711,5117)
E3: J12.7 U5.2 | length 1113.4
  Top Layer w6: v1(9739,5094) 9739,5099 9741,5101 9992.29,5101 9998.03,5106.74 9998.03,5141.83 U5.2@9999.21,5143
  Bottom Layer w6: J12.7@9118,5508 9202,5424 9437.94,5424 9735,5126.94 9735,5098 v1(9739,5094)
E4: J12.9 U5.3 | length 1258.7
  Top Layer w6: v1(9764,5073) 9764,5078 9765,5079 9998,5079 10018.89,5099.89 U5.3@10018.89,5143
  Bottom Layer w6: J12.9@9118,5608 9128,5608 9167,5569 9167,5481.63 9208.63,5440 9444.57,5440 9751,5133.57 9751,5115.94 9763,5103.94 9763,5074 v1(9764,5073)
E5: J12.11 U5.4 | length 1380
  Top Layer w6: v1(9793,5055) 9801,5063 10005,5063 10005,5063.37 10038.58,5096.95 U5.4@10038.58,5143
  Bottom Layer w6: J12.11@9118,5708 9183,5643 9183,5488.25 9215.25,5456 9451.2,5456 9788,5119.2 9788,5060 v1(9793,5055)
E6: J12.13 U5.5 | length 1509.1
  Top Layer w6: v1(9823.5,5038.5) 9832,5047 10011.63,5047 10058.26,5093.63 U5.5@10058.26,5143
  Bottom Layer w6: J12.13@9118,5808 9121.82,5808 9199,5730.82 9199,5494.88 9221.88,5472 9457.82,5472 9823.5,5106.32 v1(9823.5,5038.5)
